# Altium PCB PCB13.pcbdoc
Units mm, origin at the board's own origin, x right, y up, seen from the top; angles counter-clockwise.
Board outline 171.07 x 67.86 mm, 2 copper layers (Top Layer, Bottom Layer); 17 components, 49 nets, 124 pads, 45 vias.
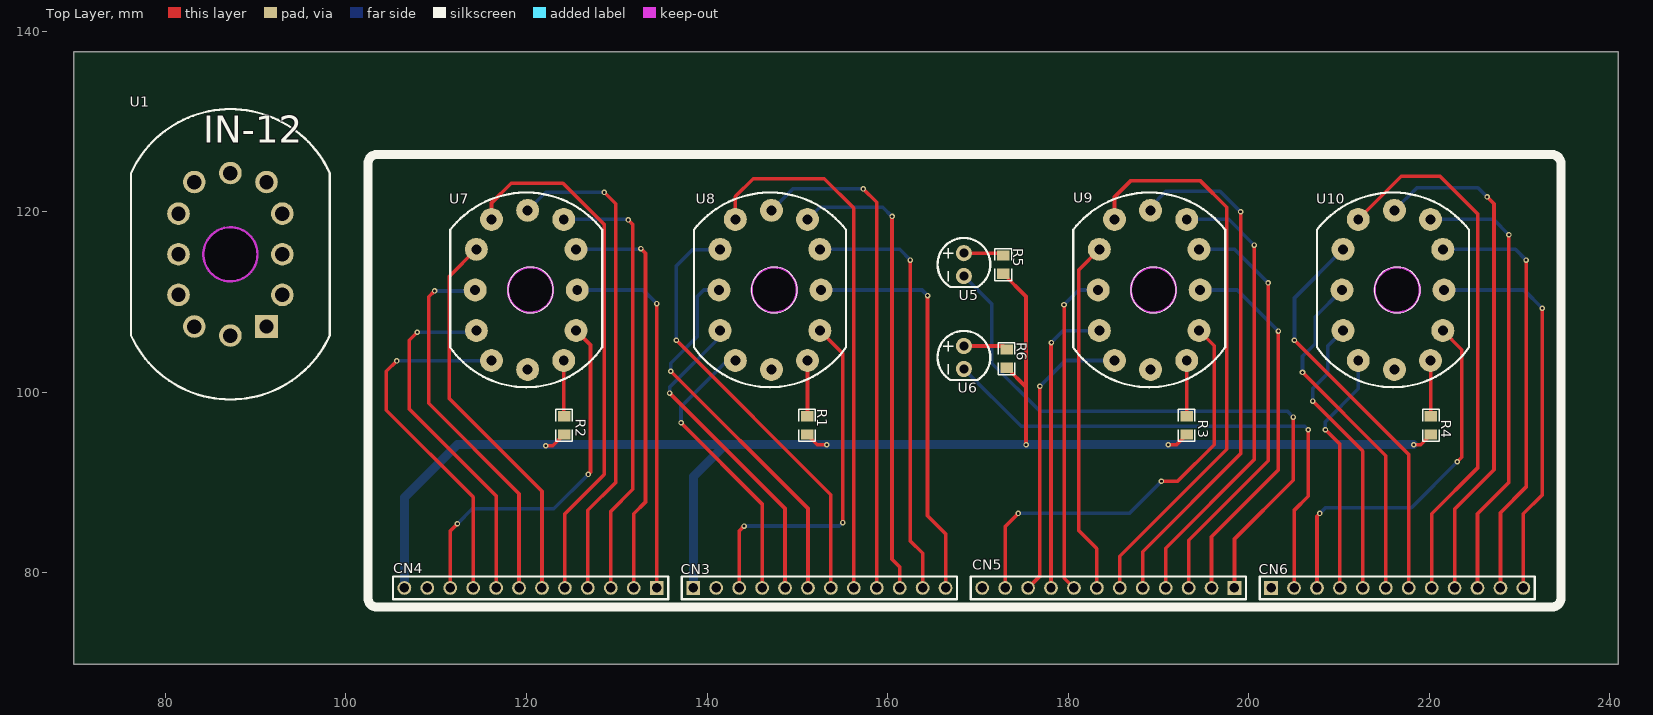
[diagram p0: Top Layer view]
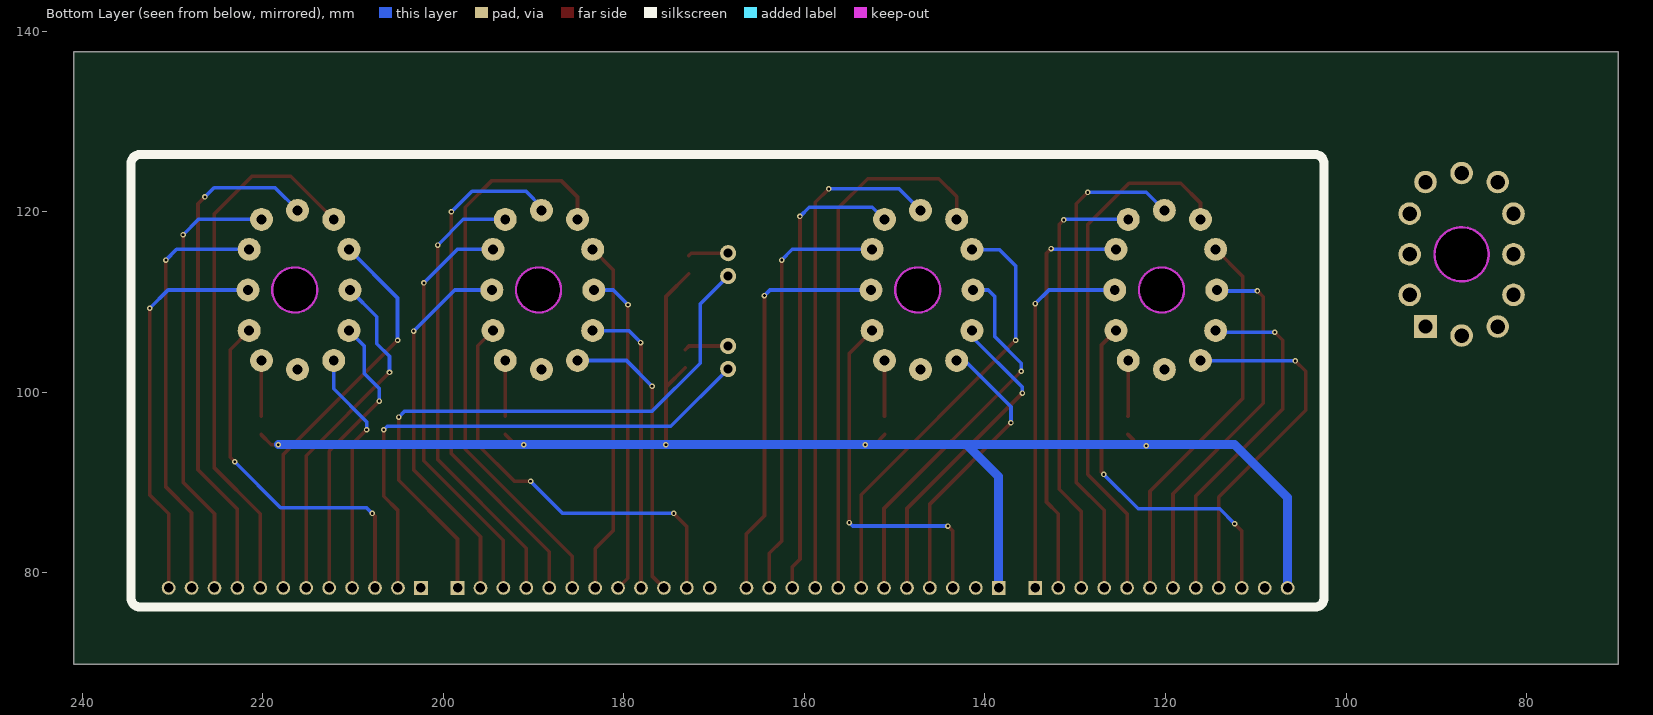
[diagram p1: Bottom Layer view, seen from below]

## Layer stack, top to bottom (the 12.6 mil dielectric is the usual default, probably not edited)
Top Layer: signal copper (thickness not stored)
Dielectric: dielectric 0.32, FR-4, Dk 4.8
Bottom Layer: signal copper (thickness not stored)

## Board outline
240.918,69.85 69.85,69.85 69.85,137.711 240.918,137.711

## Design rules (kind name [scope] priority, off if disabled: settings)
Clearance copperThickness1oz [All] p1: gap=0.178 ignorepadtopadclearanceinfootprint=FALSE except(0.102: Track-Track; 0.152: Track-SMDPad SMDPad-SMDPad Track-THPad SMDPad-THPad THPad-THPad Track-Via SMDPad-Via THPad-Via Via-Via Track-Fill SMDPad-Fill THPad-Fill Via-Fill Fill-Fill SMDPad-Region THPad-Region Via-Region Fill-Region Region-Region Track-Poly SMDPad-Poly THPad-Poly Via-Poly Fill-Poly Poly-Poly Track-Text SMDPad-Text THPad-Text Via-Text Fill-Text Region-Text Poly-Text Text-Text Track-Hole SMDPad-Hole THPad-Hole Via-Hole Fill-Hole Region-Hole Poly-Hole Text-Hole; 0.3: Track-Region Region-Poly Track-Sheet SMDPad-Sheet THPad-Sheet Via-Sheet Fill-Sheet Region-Sheet Poly-Sheet Text-Sheet Sheet-Hole)
Clearance copperThickness2oz [All] p1: gap=0.178 ignorepadtopadclearanceinfootprint=FALSE except(0.152: Track-SMDPad SMDPad-SMDPad Track-THPad SMDPad-THPad THPad-THPad Track-Via SMDPad-Via THPad-Via Via-Via Track-Fill SMDPad-Fill THPad-Fill Via-Fill Fill-Fill SMDPad-Region THPad-Region Via-Region Fill-Region Region-Region Track-Poly SMDPad-Poly THPad-Poly Via-Poly Fill-Poly Poly-Poly Track-Text SMDPad-Text THPad-Text Via-Text Fill-Text Region-Text Poly-Text Text-Text Track-Hole SMDPad-Hole THPad-Hole Via-Hole Fill-Hole Region-Hole Poly-Hole Text-Hole; 0.203: Track-Track; 0.3: Track-Region Region-Poly Track-Sheet SMDPad-Sheet THPad-Sheet Via-Sheet Fill-Sheet Region-Sheet Poly-Sheet Text-Sheet Sheet-Hole)
DiffPairsRouting differentialPair [All] p1: maxuncoupledlength=10 maxlimit=6 mostfreqgap=6 toplayer_minwidth=5 toplayer_prefwidth=10 toplayer_maxwidth=100 bottomlayer_minwidth=5 bottomlayer_prefwidth=10 bottomlayer_maxwidth=100
PasteMaskExpansion pasteMaskExpansion [All] p1:
PlaneConnect innerPlane [All] p1: planeconnectstyle=Relief reliefexpansion=0.508 reliefentries=4 reliefconductorwidth=0.254 reliefairgap=0.254
PolygonConnect copperRegion [All] p1: connectstyle=Relief reliefentries=4 reliefconductorwidth=10 polygonreliefangle="90 Angle" airgapwidth=10
RoutingVias viaSize [All] p1: viastyle="Through Hole" holewidth=12.0078 minholewidth=11.811 maxholewidth=248.0314 width=24.0158 minwidth=19.685 maxwidth=393.7008
SolderMaskExpansion solderMaskExpansion [All] p1: useseparateexpansions=TRUE expansion=2 expansionbottom=2
Width copperThickness1oz [All] p1: maxlimit=100 minlimit=5 preferedwidth=10
Width copperThickness2oz [All] p1: maxlimit=100 minlimit=8 preferedwidth=10

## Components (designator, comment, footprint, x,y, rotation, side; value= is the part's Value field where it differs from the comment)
CN3 "HB-PH3-254112PB2GOP" HDR-TH_12P-P2.54-V-M 152.441,78.327 r0 top
CN4 "HB-PH3-254112PB2GOP" HDR-TH_12P-P2.54-V-M 120.441,78.327 r180 top
CN5 "HB-PH3-254112PB2GOP" HDR-TH_12P-P2.54-V-M 184.441,78.327 r180 top
CN6 "HB-PH3-254112PB2GOP" HDR-TH_12P-P2.54-V-M 216.441,78.327 r0 top
R1 "0805W8F3302T5E" R0805 151.082,96.327 r270 top
R2 "0805W8F3302T5E" R0805 124.158,96.327 r270 top
R3 "0805W8F3302T5E" R0805 193.119,96.327 r270 top
R4 "0805W8F3302T5E" R0805 220.17,96.327 r270 top
R5 "0805W8F4702T5E" R0805 172.799,114.135 r270 top
R6 "0805W8F4702T5E" R0805 173.18,103.721 r270 top
U1 "IN-12" IN-12#1 87.201,115.278 r0 top
U5 "LTL-307E" LED-TH_BD5.9-P2.54-RD_RED 168.441,114.135 r90 top
U6 "LTL-307E" LED-TH_BD5.9-P2.54-RD_RED 168.441,103.848 r90 top
U7 "IN-12A_" IN-12#2 120.441,111.327 r0 top
U8 "IN-12A_" IN-12#2 147.441,111.327 r0 top
U9 "IN-12A_" IN-12#2 189.441,111.327 r0 top
U10 "IN-12A_" IN-12#2 216.441,111.327 r0 top

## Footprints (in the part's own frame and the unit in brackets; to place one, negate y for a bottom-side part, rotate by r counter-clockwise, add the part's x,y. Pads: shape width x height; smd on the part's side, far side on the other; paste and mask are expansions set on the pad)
HDR-TH_12P-P2.54-V-M [mil]
  rect 60x60 hole 41.34: 1(-550,0)
  round 60 hole 41.34: 2(-450,0) 3(-350,0) 4(-250,0) 5(-150,0) 6(-50,0) 7(50,0) 8(150,0) 9(250,0) 10(350,0) 11(450,0) 12(550,0)
  silkscreen extent -600,-50 600,50
IN-12#1 [mm]
  rect 2.5x2.5 hole 1.6: 1(4,-8)
  round 2.5 hole 1.6: 2(5.751,-4.501) 3(5.751,0) 4(5.751,4.501) 5(4,8.001) 6(0,8.999) 7(-4,8.001) 8(-5.751,4.501) 9(-5.751,0) 10(-5.751,-4.501) 11(-4,-8.001) 12(0,-8.999)
  Multi-Layer board cut-out: 3,0 2.703,1.302 1.87,2.345 0.668,2.925 -0.668,2.925 -1.871,2.345 -2.703,1.302 -3,0 -3,0 -2.703,-1.302 -1.87,-2.346 -0.668,-2.925 0.668,-2.925 1.871,-2.346 2.703,-1.302 3,0
  Multi-Layer keep-out circle w0.254: c0,0 r3
  silkscreen extent -11,-16.08 11,16.08
IN-12#2 [mm]
  round 2.54 hole 1.1: 0(5.047,-4.5) 1(-4.317,-7.817) 2(-6,-4.5) 3(-6.127,0) 4(-6,4.5) 5(-4.317,7.817) 6(-0.318,8.817) 7(3.682,7.817) 8(5.047,4.5) 9(5.174,0) A(3.682,-7.817) LHDP(-0.318,-8.817)
  Multi-Layer board cut-out: 2.5,0 2.16,1.244 1.246,2.152 0,2.485 -1.246,2.152 -2.16,1.244 -2.5,0 -2.5,0 -2.16,-1.244 -1.246,-2.153 0,-2.485 1.246,-2.152 2.16,-1.244 2.5,0
  Multi-Layer keep-out circle w0.254: c0,0 r2.5
  silkscreen extent -8.89,-10.77 7.94,10.79
LED-TH_BD5.9-P2.54-RD_RED [mm]
  round 1.8 hole 1: 1(-1.27,0) 2(1.27,0)
  silkscreen extent -2.49,-2.92 2.94,2.92
R0805 [mm]
  rect 1.133x1.377 smd: 1(-1,0) 2(1,0)
  silkscreen extent -1.76,-0.92 1.76,0.92

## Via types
v1: diameter 0.61, hole 0.305, Top Layer to Bottom Layer, 45 vias

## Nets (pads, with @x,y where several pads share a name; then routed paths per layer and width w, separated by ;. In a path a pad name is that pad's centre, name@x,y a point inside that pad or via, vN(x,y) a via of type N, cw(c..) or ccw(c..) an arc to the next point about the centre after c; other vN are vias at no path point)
$1N925: R5.1 U5.2 | length 4.5
  Top Layer w0.4: U5.2 172.529,115.405 R5.1
$1N929: R6.1 U6.2 | length 4.9
  Top Layer w0.4: U6.2 172.783,105.118 R6.1
$1N970: R2.1 U7.A | length 6.2
  Top Layer w0.4: U7.A 124.123,97.362 R2.1
$1N973: R1.1 U8.A | length 6.2
  Top Layer w0.4: R1.1 151.123,97.368 U8.A
$1N994: R3.1 U9.A | length 6.2
  Top Layer w0.4: R3.1 193.119,103.505 U9.A
$1N996: R4.1 U10.A | length 6.2
  Top Layer w0.4: U10.A 220.17,103.463 R4.1
G1_0: CN4.10 U7.0 | length 40.9
  Top Layer w0.4: CN4.10 111.551,84.637 v1(112.347,85.433) ; U7.0 127.079,105.236 127.079,91.148 v1(126.825,90.894)
  Bottom Layer w0.4: v1(112.347,85.433) 113.998,87.084 123.015,87.084 v1(126.825,90.894)
G1_1: CN4.9 U7.1 | length 40.1
  Top Layer w0.4: v1(105.616,103.467) 104.473,102.324 104.473,98.006 114.091,88.388 CN4.9
  Bottom Layer w0.4: v1(105.616,103.467) 116.081,103.467 U7.1
G1_2: CN4.8 U7.2 | length 39.3
  Top Layer w0.4: v1(107.902,106.642) 107.013,105.753 107.013,98.133 116.631,88.515 CN4.8
  Bottom Layer w0.4: v1(107.902,106.642) 114.256,106.642 U7.2
G1_3: 
G1_4: CN4.6 U7.4 | length 43
  Top Layer w0.4: U7.4 111.458,112.844 111.458,99.276 121.711,89.023 CN4.6
G1_5: CN4.5 U7.5 | length 59.2
  Top Layer w0.4: U7.5 116.123,120.96 118.316,123.152 124.031,123.152 128.603,118.58 128.603,90.894 124.251,86.542 CN4.5
G1_6: CN4.4 U7.6 | length 54.9
  Top Layer w0.4: CN4.4 126.791,86.923 129.873,90.005 129.873,120.866 v1(128.603,122.136)
  Bottom Layer w0.4: U7.6 122.115,122.136 v1(128.603,122.136)
G1_7: CN4.3 U7.7 | length 49.2
  Top Layer w0.4: CN4.3 129.331,86.796 131.778,89.243 131.778,118.58 v1(131.27,119.088)
  Bottom Layer w0.4: U7.7 131.213,119.144 v1(131.27,119.088)
G1_8: CN4.2 U7.8 | length 45.6
  Top Layer w0.4: CN4.2 131.871,86.542 133.175,87.846 133.175,115.405 v1(132.667,115.913)
  Bottom Layer w0.4: U7.8 132.581,115.827 v1(132.667,115.913)
G1_9: CN4.1 U7.9 | length 40.9
  Top Layer w0.4: CN4.1 v1(134.411,109.817)
  Bottom Layer w0.4: U7.9 132.901,111.327 v1(134.411,109.817)
G2_0: CN3.3 U8.0 | length 40.5
  Top Layer w0.4: CN3.3 143.551,84.633 v1(144.097,85.179) ; U8.0 155.019,104.296 v1(155.019,85.56)
  Bottom Layer w0.4: v1(144.097,85.179) 154.638,85.179 v1(155.019,85.56)
G2_1: CN3.4 U8.1 | length 31.9
  Top Layer w0.4: v1(137.112,96.609) 146.091,87.63 CN3.4
  Bottom Layer w0.4: v1(137.112,96.609) 137.112,98.387 142.234,103.51 U8.1
G2_2: CN3.5 U8.2 | length 36.1
  Top Layer w0.4: v1(135.842,99.911) 148.631,87.122 CN3.5
  Bottom Layer w0.4: v1(135.842,99.911) 135.842,100.546 141.441,106.145 U8.2
G2_3: CN3.6 U8.3 | length 42.5
  Top Layer w0.4: v1(135.969,102.324) 151.171,87.122 CN3.6
  Bottom Layer w0.4: v1(135.969,102.324) 135.969,103.213 138.89,106.134 138.89,110.579 139.638,111.327 U8.3
G2_4: CN3.7 U8.4 | length 48.4
  Top Layer w0.4: v1(136.604,105.753) 153.711,88.646 CN3.7
  Bottom Layer w0.4: v1(136.604,105.753) 136.604,114.008 138.382,115.786 141.4,115.786 U8.4
G2_5: CN3.8 U8.5 | length 59.9
  Top Layer w0.4: U8.5 143.123,121.671 145.113,123.66 152.987,123.66 156.251,120.396 CN3.8
G2_6: CN3.9 U8.6 | length 56
  Top Layer w0.4: v1(157.305,122.517) 158.791,121.031 CN3.9
  Bottom Layer w0.4: U8.6 149.496,122.517 v1(157.305,122.517)
G2_7: CN3.10 U8.7 | length 51.8
  Top Layer w0.4: v1(160.48,119.469) 160.48,81.496 161.331,80.645 CN3.10
  Bottom Layer w0.4: U8.7 152.464,120.485 159.464,120.485 v1(160.48,119.469)
G2_8: CN3.11 U8.8 | length 47.4
  Top Layer w0.4: v1(162.512,114.643) 162.512,83.528 163.871,82.169 CN3.11
  Bottom Layer w0.4: U8.8 161.328,115.827 v1(162.512,114.643)
G2_9: CN3.12 U8.9 | length 45.3
  Top Layer w0.4: v1(164.417,110.706) 164.417,86.322 166.411,84.328 CN3.12
  Bottom Layer w0.4: U8.9 163.796,111.327 v1(164.417,110.706)
G3_0: CN5.11 U9.0 | length 47
  Top Layer w0.4: CN5.11 173.011,85.137 v1(174.45,86.576) ; v1(190.325,90.132) 192.103,90.132 196.167,94.196 196.167,105.148 U9.0
  Bottom Layer w0.4: v1(174.45,86.576) 186.769,86.576 v1(190.325,90.132)
G3_1: CN5.10 U9.1 | length 32.3
  Top Layer w0.4: CN5.10 176.863,79.639 v1(176.863,100.673)
  Bottom Layer w0.4: v1(176.863,100.673) 179.699,103.51 U9.1
G3_2: CN5.9 U9.2 | length 33
  Top Layer w0.4: CN5.9 178.091,105.457 v1(178.133,105.499)
  Bottom Layer w0.4: v1(178.133,105.499) 179.461,106.827 U9.2
G3_3: CN5.8 U9.3 | length 36.3
  Top Layer w0.4: v1(179.53,109.69) 179.549,109.671 179.549,79.409 CN5.8
  Bottom Layer w0.4: v1(179.53,109.69) 181.167,111.327 U9.3
G3_4: CN5.7 U9.4 | length 39.3
  Top Layer w0.4: CN5.7 183.171,82.681 181.181,84.671 181.181,113.567 U9.4
G3_5: CN5.6 U9.5 | length 63.9
  Top Layer w0.4: U9.5 185.123,121.634 186.896,123.406 194.643,123.406 197.564,120.485 197.564,93.688 185.711,81.835 CN5.6
G3_6: CN5.5 U9.6 | length 58.2
  Top Layer w0.4: CN5.5 188.251,82.343 199.088,93.18 v1(199.088,119.977)
  Bottom Layer w0.4: U9.6 189.123,120.554 190.833,122.263 196.802,122.263 v1(199.088,119.977)
G3_7: CN5.4 U9.7 | length 50.7
  Top Layer w0.4: CN5.4 190.791,82.724 200.612,92.545 v1(200.612,116.294)
  Bottom Layer w0.4: U9.7 197.761,119.144 v1(200.612,116.294)
G3_8: CN5.3 U9.8 | length 46.6
  Top Layer w0.4: CN5.3 193.331,83.613 202.136,92.418 v1(202.136,112.103)
  Bottom Layer w0.4: U9.8 198.412,115.827 v1(202.136,112.103)
G3_9: CN5.2 U9.9 | length 42.1
  Top Layer w0.4: CN5.2 195.871,83.994 203.279,91.402 v1(203.279,106.769)
  Bottom Layer w0.4: U9.9 198.721,111.327 v1(203.279,106.769)
G4_0: CN6.3 U10.0 | length 41.6
  Top Layer w0.4: CN6.3 207.551,86.276 v1(207.851,86.576) ; U10.0 223.599,104.716 223.599,92.799 v1(223.091,92.291)
  Bottom Layer w0.4: v1(207.851,86.576) 208.486,87.211 218.011,87.211 v1(223.091,92.291)
G4_1: CN6.4 U10.1 | length 27.4
  Top Layer w0.4: v1(208.486,95.847) 210.091,94.242 CN6.4
  Bottom Layer w0.4: v1(208.486,95.847) 208.486,96.736 212.123,100.374 U10.1
G4_2: CN6.5 U10.2 | length 32.2
  Top Layer w0.4: v1(207.089,99.022) 212.631,93.48 CN6.5
  Bottom Layer w0.4: v1(207.089,99.022) 207.089,100.419 208.74,102.07 208.74,105.126 U10.2
G4_3: CN6.6 U10.3 | length 38.6
  Top Layer w0.4: v1(205.946,102.197) 215.171,92.972 CN6.6
  Bottom Layer w0.4: v1(205.946,102.197) 205.946,103.975 207.343,105.372 207.343,108.356 U10.3
G4_4: CN6.7 U10.4 | length 45
  Top Layer w0.4: v1(205.057,105.753) 217.711,93.099 CN6.7
  Bottom Layer w0.4: v1(205.057,105.753) 205.057,110.443 U10.4
G4_5: CN6.8 U10.5 | length 60.5
  Top Layer w0.4: U10.5 216.893,123.914 221.186,123.914 225.377,119.723 225.377,91.656 220.251,86.53 CN6.8
G4_6: CN6.9 U10.6 | length 57.1
  Top Layer w0.4: CN6.9 222.791,87.038 227.155,91.402 227.155,120.866 v1(226.393,121.628)
  Bottom Layer w0.4: U10.6 218.623,122.644 225.377,122.644 v1(226.393,121.628)
G4_7: CN6.10 U10.7 | length 49.9
  Top Layer w0.4: CN6.10 225.331,86.53 228.806,90.005 v1(228.806,117.437)
  Bottom Layer w0.4: U10.7 227.098,119.144 v1(228.806,117.437)
G4_8: CN6.11 U10.8 | length 47.2
  Top Layer w0.4: CN6.11 227.871,86.657 230.711,89.497 v1(230.711,114.643)
  Bottom Layer w0.4: U10.8 229.527,115.827 v1(230.711,114.643)
G4_9: CN6.12 U10.9 | length 43.6
  Top Layer w0.4: CN6.12 230.411,86.53 232.489,88.608 v1(232.489,109.309)
  Bottom Layer w0.4: U10.9 230.471,111.327 v1(232.489,109.309)
HGD_1: CN5.1 U5.1 | length 68.4
  Top Layer w0.4: CN5.1 198.411,83.74 204.93,90.259 v1(204.93,97.244)
  Bottom Layer w0.4: U5.1 171.529,109.777 171.529,103.213 176.863,97.879 204.295,97.879 v1(204.93,97.244)
HGD_2: CN6.2 U6.1 | length 59.1
  Top Layer w0.4: CN6.2 205.011,86.911 206.581,88.481 v1(206.581,95.847)
  Bottom Layer w0.4: U6.1 174.791,96.228 206.2,96.228 v1(206.581,95.847)
HV: CN3.1 CN4.12 R1.2 R2.2 R3.2 R4.2 R5.2 R6.2 | length 174.6
  Top Layer w0.4: v1(122.126,94.069) 122.9,94.069 R2.2 ; R1.2 152.213,94.196 v1(153.241,94.196) ; R5.2 175.325,110.608 175.325,100.575 ; R6.2 175.325,100.575 ; v1(175.325,94.196) 175.325,100.575 ; v1(191.087,94.196) 191.988,94.196 R3.2 ; v1(218.265,94.196) 219.039,94.196 R4.2
  Bottom Layer w1: CN4.12 106.471,88.32 112.347,94.196 142.024,94.196 ; CN3.1 138.471,90.643 142.024,94.196 ; v1(218.265,94.196) v1(191.087,94.196) v1(175.325,94.196) v1(153.241,94.196) 142.024,94.196
pads on no net: CN3.2 CN4.7 CN4.11 CN5.12 CN6.1 U1.1 U1.2 U1.3 U1.4 U1.5 U1.6 U1.7 U1.8 U1.9 U1.10 U1.11 U1.12 U7.3 U7.LHDP U8.LHDP U9.LHDP U10.LHDP
copper on no net: | length 41.8
  Top Layer w0.4: v1(109.807,111.214) 109.172,110.579 109.172,98.768 119.171,88.769 119.171,78.327
  Bottom Layer w0.4: v1(109.807,111.214) 114.201,111.214 114.314,111.327

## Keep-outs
Board Outline Layer:
  lines w0.254: 102.441,77.327 ccw(c103.441,77.327) 103.441,76.327 233.441,76.327 ccw(c233.441,77.327) 234.441,77.327 234.441,125.327 ccw(c233.441,125.327) 233.441,126.327 103.441,126.327 ccw(c103.441,125.327) 102.441,125.327 102.441,77.327

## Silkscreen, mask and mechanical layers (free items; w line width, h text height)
Top Silkscreen Layer:
  lines w1: 102.441,77.2 ccw(c103.441,77.2) 103.441,76.2 233.568,76.2 ccw(c233.568,77.2) 234.568,77.2 234.568,125.327 ccw(c233.568,125.327) 233.568,126.327 103.441,126.327 ccw(c103.441,125.327) 102.441,125.327 102.441,77.2
Bottom Silkscreen Layer:
  lines w1: 102.441,77.2 ccw(c103.441,77.2) 103.441,76.2 233.568,76.2 ccw(c233.568,77.2) 234.568,77.2 234.568,125.327 ccw(c233.568,125.327) 233.568,126.327 103.441,126.327 ccw(c103.441,125.327) 102.441,125.327 102.441,77.2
